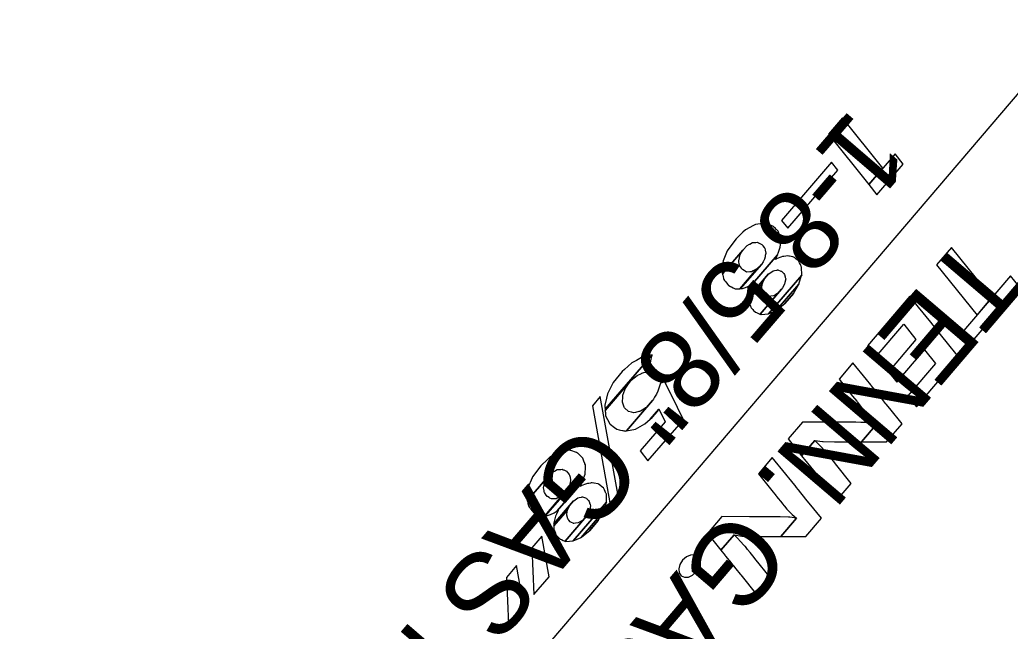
# Model space of a CAD drawing. Extents: x 3962991 to 3983549, y 181631 to 204078.
# Drawn here: x 3970389 to 3970895, y 196655 to 196968 of the extents above; entities that cross this region are included whole.
import ezdxf

# ---------------------------------------------------------------- set-up
doc = ezdxf.new("R2010")
doc.units = 0
for name, color, linetype in [('V-ANNO-MASK', 7, 'Continuous'), ('V-ANNO-MASK2', 7, 'Continuous'), ('V-UTIL-IDEN', 7, 'Continuous'), ('V-UTIL-LINE', 7, 'Continuous')]:
    doc.layers.add(name, color=color, linetype=linetype)

msp = doc.modelspace()

# ---------------------------------------------------------------- linework, layer by layer
at = {"layer": 'V-ANNO-MASK2'}
for points in [[(3970830.22, 196891.79), (3970809.67, 196917.48), (3970802.46, 196909.1), (3970823.01, 196883.41)], [(3970840.72, 196893.86), (3970836.52, 196899.13), (3970823.01, 196883.41), (3970827.21, 196878.14)], [(3970807.3, 196890.7), (3970804.05, 196894.76), (3970778.46, 196864.97), (3970781.7, 196860.92)], [(3970758.68, 196858.95), (3970755.12, 196855.59), (3970750.89, 196849.88), (3970750.65, 196849.33), (3970748.45, 196844.25), (3970748.36, 196843.47), (3970747.86, 196839.08), (3970748.1, 196838.07), (3970748.19, 196837.68), (3970758.53, 196849.71), (3970760.9, 196852.2), (3970762.09, 196852.85), (3970762.1, 196852.85), (3970763.47, 196853.59), (3970764.68, 196853.68), (3970765.29, 196853.73), (3970766.09, 196853.79), (3970766.58, 196853.56), (3970766.91, 196853.39), (3970768.32, 196852.71), (3970768.82, 196852.06), (3970768.9, 196851.96), (3970769.53, 196851.15), (3970769.82, 196850.75), (3970770.04, 196849.65), (3970770.34, 196848.12), (3970770.31, 196848), (3970770.1, 196846.95), (3970769.96, 196846.26), (3970769.74, 196845.18), (3970768.94, 196843.8), (3970768.16, 196842.47), (3970757.46, 196830.02), (3970758.51, 196830.05), (3970759.99, 196830.64), (3970761.98, 196831.43), (3970763.55, 196832.46), (3970776.39, 196847.39), (3970776.85, 196848.73), (3970777.72, 196851.27), (3970777.81, 196852.5), (3970777.89, 196853.79), (3970777.93, 196854.27), (3970777.96, 196854.75), (3970778.02, 196855.64), (3970777.89, 196856.02), (3970777.68, 196856.58), (3970777.66, 196856.65), (3970777.18, 196857.96), (3970776.83, 196858.9), (3970776.64, 196859.42), (3970775.92, 196860.13), (3970775.83, 196860.22), (3970775.26, 196860.78), (3970774.17, 196861.85), (3970773.92, 196862.09), (3970773.39, 196862.28), (3970772.81, 196862.49), (3970772.38, 196862.65), (3970771.52, 196862.95), (3970770.95, 196863.15), (3970770.47, 196863.33), (3970770.28, 196863.39), (3970769.96, 196863.5), (3970768.73, 196863.36), (3970765.08, 196862.92), (3970763.99, 196862.33), (3970759.92, 196860.12)], [(3970758.12, 196848.97), (3970758.53, 196849.71), (3970748.19, 196837.68), (3970748.24, 196837.46), (3970748.24, 196837.47), (3970748.37, 196836.88), (3970748.38, 196836.89), (3970748.53, 196836.2), (3970748.77, 196835.17), (3970748.89, 196834.65), (3970749.26, 196834.21), (3970749.6, 196833.8), (3970749.83, 196833.52), (3970750.8, 196832.33), (3970751.32, 196831.7), (3970751.4, 196831.6), (3970752.33, 196831.14), (3970752.34, 196831.14), (3970752.78, 196830.92), (3970753.6, 196830.52), (3970754.72, 196829.96), (3970754.78, 196829.92), (3970755.49, 196829.95), (3970755.96, 196829.96), (3970756.68, 196829.99), (3970757.08, 196830), (3970765.78, 196840.13), (3970765.08, 196839.77), (3970763.81, 196839.1), (3970762.98, 196838.67), (3970762.27, 196838.64), (3970762.18, 196838.64), (3970760.5, 196838.55), (3970759.74, 196839.01), (3970759.31, 196839.26), (3970758.44, 196839.78), (3970758.32, 196839.85), (3970757.85, 196840.53), (3970756.96, 196841.81), (3970756.88, 196842.26), (3970756.76, 196842.93), (3970756.63, 196843.65), (3970756.52, 196844.2), (3970756.83, 196845.86), (3970757.03, 196846.95)], [(3970776.21, 196847.02), (3970776.38, 196847.39), (3970763.55, 196832.46), (3970763.9, 196832.68), (3970763.12, 196830.84), (3970762.63, 196829.69), (3970762.1, 196827.73), (3970761.74, 196826.38), (3970761.75, 196825.83), (3970771.82, 196837.55), (3970771.98, 196837.66), (3970774.08, 196839.08), (3970774.12, 196839.09), (3970774.75, 196839.24), (3970775.98, 196839.52), (3970776.23, 196839.57), (3970776.23, 196839.58), (3970776.44, 196839.62), (3970778.04, 196839.06), (3970778.33, 196838.95), (3970778.34, 196838.96), (3970778.47, 196838.9), (3970778.72, 196838.63), (3970779.55, 196837.71), (3970779.93, 196837.29), (3970780.24, 196836.12), (3970780.32, 196835.86), (3970780.35, 196835.72), (3970780.53, 196835.05), (3970780.17, 196833.2), (3970779.98, 196832.26), (3970778.94, 196830.48), (3970778.47, 196829.68), (3970767.54, 196816.96), (3970767.88, 196816.82), (3970767.92, 196816.82), (3970771.68, 196817.1), (3970788.73, 196836.93), (3970788.67, 196840.97), (3970788.67, 196841), (3970788.5, 196841.36), (3970788.42, 196841.52), (3970788.25, 196841.89), (3970788.04, 196842.36), (3970787.61, 196843.29), (3970787.34, 196843.85), (3970787.29, 196843.97), (3970787.18, 196844.2), (3970786.4, 196844.82), (3970785.95, 196845.17), (3970784.99, 196845.92), (3970784.7, 196846.15), (3970784.59, 196846.23), (3970784.26, 196846.3), (3970782.47, 196846.64), (3970782.32, 196846.67), (3970782.15, 196846.7), (3970781.3, 196846.86), (3970780.69, 196846.74), (3970780.66, 196846.74), (3970779.61, 196846.53), (3970779.53, 196846.52), (3970778.95, 196846.41), (3970777.99, 196846.22), (3970776.13, 196845.39), (3970775.31, 196845.03)], [(3970886.13, 196825.47), (3970865.39, 196851.15), (3970857.76, 196842.2), (3970878.49, 196816.52)], [(3970768.17, 196842.47), (3970765.78, 196840.13), (3970757.08, 196830), (3970757.46, 196830.02)], [(3970769.88, 196835.21), (3970771.82, 196837.55), (3970761.75, 196825.83), (3970761.75, 196825.75), (3970761.76, 196824.75), (3970761.76, 196824.71), (3970768.66, 196832.74), (3970768.7, 196832.83)], [(3970768.56, 196832.04), (3970768.66, 196832.74), (3970761.76, 196824.71), (3970761.77, 196824.13), (3970761.78, 196822.99), (3970761.84, 196822.83), (3970761.9, 196822.7), (3970762.54, 196821.02), (3970762.66, 196820.72), (3970762.71, 196820.56), (3970762.86, 196820.17), (3970763.72, 196819.3), (3970764.12, 196818.9), (3970764.83, 196818.18), (3970764.98, 196818.01), (3970765.1, 196817.97), (3970765.65, 196817.74), (3970766.56, 196817.37), (3970767.02, 196817.18), (3970767.37, 196817.02), (3970767.38, 196817.03), (3970767.53, 196816.96), (3970778.47, 196829.68), (3970776.42, 196827.55), (3970775.47, 196827.01), (3970774.25, 196826.32), (3970772.87, 196826.13), (3970772.01, 196826.02), (3970771.91, 196826.07), (3970771.69, 196826.17), (3970770.72, 196826.58), (3970770.17, 196826.81), (3970769.38, 196827.76), (3970769.15, 196828.05), (3970769.06, 196828.16), (3970768.86, 196828.39), (3970768.37, 196830.24), (3970768.33, 196830.38), (3970768.37, 196830.67)], [(3970788.71, 196836.87), (3970788.72, 196836.93), (3970771.68, 196817.1), (3970771.71, 196817.09), (3970775.7, 196818.88), (3970787.31, 196832.4)], [(3970787.03, 196831.91), (3970787.31, 196832.39), (3970775.7, 196818.88), (3970775.91, 196818.98), (3970780.15, 196822.46), (3970784.45, 196827.47)], [(3970899.97, 196831.09), (3970895.58, 196836.56), (3970869.72, 196806.23), (3970874.11, 196800.76)], [(3970780.43, 196822.69), (3970784.45, 196827.46), (3970780.15, 196822.46)], [(3970848.49, 196820.61), (3970844.04, 196826.11), (3970822.38, 196800.71), (3970826.82, 196795.2), (3970840.93, 196811.75), (3970847.21, 196803.99), (3970833.1, 196787.44), (3970837.44, 196782.07), (3970851.54, 196798.62), (3970857.19, 196791.61), (3970843.08, 196775.06), (3970847.51, 196769.56), (3970869.17, 196794.97), (3970864.74, 196800.46), (3970859.09, 196807.47), (3970854.76, 196812.84)], [(3970698.04, 196788.68), (3970696.89, 196787.66), (3970692.28, 196781.98), (3970691.07, 196779.55), (3970689.35, 196776.13), (3970688.83, 196773.92), (3970687.97, 196770.32), (3970688, 196769.9), (3970688.12, 196768.25), (3970712.13, 196796.2), (3970710.31, 196795.85), (3970709.76, 196795.68), (3970706.7, 196794.72), (3970704.1, 196793.29), (3970701.78, 196792.02)], [(3970711.97, 196795.26), (3970712.13, 196796.19), (3970688.12, 196768.25), (3970688.17, 196767.57), (3970701.35, 196782.91), (3970703.04, 196784.33), (3970704.54, 196785.59), (3970706.7, 196786.55), (3970706.71, 196786.56), (3970706.97, 196786.68), (3970707.85, 196787.07), (3970710.28, 196787.46), (3970710.59, 196787.51), (3970710.66, 196787.91), (3970711.21, 196790.98), (3970711.35, 196791.77), (3970711.39, 196792.01), (3970711.74, 196793.96), (3970711.85, 196794.57)], [(3970821.89, 196783.43), (3970814.96, 196792), (3970807.87, 196783.69), (3970814.74, 196775.04), (3970816.9, 196772.33), (3970817.11, 196772.06), (3970817.11, 196772.06), (3970819.93, 196768.5), (3970820.01, 196768.4), (3970821.12, 196767), (3970822.47, 196765.56), (3970824.74, 196763.12), (3970825.15, 196762.77), (3970827.31, 196760.88), (3970819.36, 196751.55), (3970832.16, 196751.56), (3970840.09, 196760.86), (3970833.87, 196768.57), (3970832.04, 196770.85), (3970831.7, 196771.28), (3970829.58, 196773.89), (3970828.33, 196775.45), (3970827.2, 196776.84), (3970827.13, 196776.94), (3970824.28, 196780.47), (3970824.07, 196780.73)], [(3970698.63, 196779.19), (3970701.35, 196782.91), (3970688.17, 196767.57), (3970688.2, 196767.06), (3970688.24, 196766.61), (3970688.34, 196765.19), (3970688.35, 196765.01), (3970688.55, 196764.62), (3970689.32, 196763.07), (3970690.46, 196760.77), (3970690.71, 196760.58), (3970692.94, 196758.86), (3970694.05, 196758), (3970695.31, 196757.74), (3970695.32, 196757.75), (3970695.9, 196757.62), (3970697.07, 196757.38), (3970697.25, 196757.34), (3970697.62, 196757.27), (3970698.22, 196757.15), (3970698.56, 196757.07), (3970698.87, 196757.14), (3970699.08, 196757.18), (3970712.44, 196772.73), (3970709.42, 196769.41), (3970708.83, 196769.01), (3970707.87, 196768.37), (3970706.2, 196767.24), (3970705.66, 196767.12), (3970705.38, 196767.06), (3970703.66, 196766.65), (3970702.8, 196766.45), (3970701.59, 196766.78), (3970700.08, 196767.18), (3970698, 196769.06), (3970697.88, 196769.39), (3970696.93, 196771.92), (3970697.11, 196774.57), (3970697.16, 196775.25), (3970697.17, 196775.46), (3970698.28, 196778.29)], [(3970718.41, 196782.21), (3970716.49, 196781.58), (3970715.67, 196779.03), (3970715.47, 196778.55), (3970715.48, 196778.55), (3970715.09, 196777.59), (3970714.46, 196776.04), (3970713.47, 196774.42), (3970712.85, 196773.4), (3970712.43, 196772.72), (3970699.08, 196757.18), (3970703.62, 196758.12), (3970708.48, 196760.75), (3970711.16, 196763.16), (3970715.61, 196768.34), (3970715.69, 196768.18), (3970718.8, 196761.78), (3970706.02, 196746.9), (3970710.05, 196741.81), (3970728.15, 196762.88), (3970725.12, 196769.13), (3970722.01, 196775.53), (3970721.93, 196775.69), (3970721.72, 196776.14), (3970720.77, 196778.07), (3970719.42, 196780.86), (3970719.36, 196780.98), (3970719.27, 196781.17), (3970719.12, 196781.46), (3970718.87, 196781.99), (3970718.71, 196782.31)], [(3970695.02, 196723.15), (3970685.66, 196774.75), (3970681.59, 196770.01), (3970690.95, 196718.42)], [(3970714.84, 196767.19), (3970715.61, 196768.34), (3970711.16, 196763.16), (3970712.13, 196764.03)], [(3970712.58, 196764.43), (3970714.84, 196767.18), (3970712.13, 196764.03), (3970712.57, 196764.43)], [(3970803.32, 196761.65), (3970789.16, 196761.73), (3970781.74, 196753.03), (3970788.66, 196744.45), (3970795.38, 196752.34), (3970799.32, 196751.7), (3970799.75, 196751.7), (3970805.47, 196751.55), (3970805.64, 196751.55), (3970807.95, 196751.55), (3970810.53, 196751.55), (3970814.88, 196751.55), (3970815.58, 196751.55), (3970819.36, 196751.55), (3970827.31, 196760.88), (3970823.96, 196761.38), (3970823.28, 196761.41), (3970819.06, 196761.56), (3970816.5, 196761.58), (3970814.21, 196761.59), (3970814.04, 196761.59), (3970808.21, 196761.62), (3970807.78, 196761.63)], [(3970797.83, 196749.95), (3970795.38, 196752.34), (3970788.66, 196744.45), (3970790.84, 196741.75), (3970791.05, 196741.49), (3970793.9, 196737.97), (3970793.98, 196737.86), (3970795.1, 196736.47), (3970796.35, 196734.92), (3970798.47, 196732.3), (3970798.8, 196731.87), (3970798.81, 196731.88), (3970806.86, 196721.88), (3970814.05, 196730.31), (3970806.01, 196740.32), (3970805.67, 196740.75), (3970803.56, 196743.37), (3970802.31, 196744.93), (3970801.18, 196746.32), (3970801.1, 196746.41), (3970798.06, 196749.72)], [(3970658.78, 196742.7), (3970655.22, 196739.35), (3970650.99, 196733.64), (3970650.75, 196733.09), (3970648.55, 196728.01), (3970648.46, 196727.22), (3970647.96, 196722.83), (3970648.2, 196721.82), (3970648.29, 196721.44), (3970658.63, 196733.47), (3970661, 196735.96), (3970662.19, 196736.6), (3970662.2, 196736.61), (3970663.57, 196737.35), (3970664.78, 196737.44), (3970665.39, 196737.49), (3970666.19, 196737.54), (3970666.68, 196737.31), (3970667.01, 196737.15), (3970668.42, 196736.47), (3970668.92, 196735.82), (3970669, 196735.72), (3970669.63, 196734.9), (3970669.92, 196734.5), (3970670.14, 196733.41), (3970670.44, 196731.88), (3970670.41, 196731.76), (3970670.2, 196730.71), (3970670.06, 196730.02), (3970669.84, 196728.94), (3970669.04, 196727.56), (3970668.26, 196726.22), (3970657.56, 196713.77), (3970658.61, 196713.8), (3970660.09, 196714.4), (3970662.08, 196715.18), (3970663.65, 196716.22), (3970676.49, 196731.15), (3970676.95, 196732.48), (3970677.82, 196735.03), (3970677.91, 196736.26), (3970678, 196737.55), (3970678.03, 196738.02), (3970678.06, 196738.51), (3970678.12, 196739.4), (3970677.99, 196739.77), (3970677.79, 196740.33), (3970677.76, 196740.4), (3970677.28, 196741.72), (3970676.93, 196742.66), (3970676.74, 196743.18), (3970676.02, 196743.89), (3970675.93, 196743.98), (3970675.36, 196744.54), (3970674.28, 196745.6), (3970674.02, 196745.85), (3970673.49, 196746.04), (3970672.91, 196746.25), (3970672.48, 196746.4), (3970671.62, 196746.71), (3970671.05, 196746.91), (3970670.57, 196747.09), (3970670.38, 196747.15), (3970670.06, 196747.26), (3970668.83, 196747.12), (3970665.18, 196746.68), (3970664.09, 196746.09), (3970660.02, 196743.88)], [(3970780.6, 196735), (3970773.68, 196743.58), (3970766.59, 196735.26), (3970773.45, 196726.62), (3970775.62, 196723.9), (3970775.82, 196723.63), (3970775.83, 196723.64), (3970778.65, 196720.08), (3970778.73, 196719.97), (3970779.84, 196718.57), (3970781.19, 196717.13), (3970783.46, 196714.69), (3970783.86, 196714.35), (3970786.03, 196712.45), (3970778.08, 196703.13), (3970790.88, 196703.13), (3970798.81, 196712.43), (3970792.59, 196720.15), (3970790.75, 196722.43), (3970790.41, 196722.85), (3970788.29, 196725.47), (3970787.04, 196727.02), (3970785.92, 196728.41), (3970785.84, 196728.52), (3970782.99, 196732.04), (3970782.78, 196732.3)], [(3970658.23, 196732.73), (3970658.63, 196733.47), (3970648.29, 196721.44), (3970648.34, 196721.22), (3970648.34, 196721.23), (3970648.47, 196720.63), (3970648.48, 196720.64), (3970648.63, 196719.96), (3970648.87, 196718.93), (3970648.99, 196718.4), (3970649.36, 196717.96), (3970649.7, 196717.55), (3970649.93, 196717.27), (3970650.91, 196716.09), (3970651.42, 196715.46), (3970651.5, 196715.36), (3970652.43, 196714.89), (3970652.44, 196714.9), (3970652.88, 196714.67), (3970653.7, 196714.27), (3970654.82, 196713.71), (3970654.88, 196713.68), (3970655.59, 196713.7), (3970656.06, 196713.72), (3970656.78, 196713.74), (3970657.18, 196713.76), (3970665.89, 196723.89), (3970665.18, 196723.52), (3970663.91, 196722.86), (3970663.08, 196722.43), (3970662.37, 196722.39), (3970662.28, 196722.39), (3970660.6, 196722.31), (3970659.84, 196722.77), (3970659.41, 196723.02), (3970658.54, 196723.54), (3970658.42, 196723.6), (3970657.95, 196724.28), (3970657.06, 196725.57), (3970656.98, 196726.02), (3970656.86, 196726.68), (3970656.73, 196727.41), (3970656.62, 196727.95), (3970656.93, 196729.62), (3970657.13, 196730.71)], [(3970676.31, 196730.77), (3970676.48, 196731.14), (3970663.65, 196716.22), (3970664, 196716.44), (3970663.22, 196714.6), (3970662.73, 196713.45), (3970662.2, 196711.48), (3970661.84, 196710.14), (3970661.85, 196709.58), (3970671.92, 196721.3), (3970672.08, 196721.42), (3970674.18, 196722.84), (3970674.22, 196722.85), (3970674.85, 196722.99), (3970676.08, 196723.28), (3970676.33, 196723.33), (3970676.33, 196723.34), (3970676.54, 196723.38), (3970678.14, 196722.82), (3970678.43, 196722.71), (3970678.44, 196722.72), (3970678.57, 196722.66), (3970678.82, 196722.38), (3970679.65, 196721.47), (3970680.03, 196721.05), (3970680.34, 196719.88), (3970680.42, 196719.61), (3970680.45, 196719.47), (3970680.63, 196718.81), (3970680.27, 196716.96), (3970680.08, 196716.02), (3970679.04, 196714.24), (3970678.57, 196713.44), (3970667.64, 196700.72), (3970667.98, 196700.57), (3970668.02, 196700.58), (3970671.78, 196700.85), (3970688.83, 196720.69), (3970688.77, 196724.73), (3970688.77, 196724.76), (3970688.6, 196725.11), (3970688.53, 196725.28), (3970688.35, 196725.64), (3970688.14, 196726.11), (3970687.71, 196727.04), (3970687.44, 196727.61), (3970687.39, 196727.73), (3970687.28, 196727.95), (3970686.5, 196728.58), (3970686.05, 196728.92), (3970685.09, 196729.68), (3970684.8, 196729.91), (3970684.69, 196729.99), (3970684.36, 196730.06), (3970682.57, 196730.4), (3970682.43, 196730.42), (3970682.25, 196730.45), (3970681.4, 196730.61), (3970680.79, 196730.5), (3970680.76, 196730.49), (3970679.71, 196730.29), (3970679.63, 196730.27), (3970679.05, 196730.16), (3970678.1, 196729.97), (3970676.23, 196729.15), (3970675.41, 196728.78)], [(3970668.27, 196726.23), (3970665.88, 196723.88), (3970657.18, 196713.76), (3970657.56, 196713.77)], [(3970669.98, 196718.97), (3970671.92, 196721.3), (3970661.85, 196709.58), (3970661.85, 196709.51), (3970661.86, 196708.51), (3970661.86, 196708.47), (3970668.76, 196716.5), (3970668.8, 196716.59)], [(3970688.81, 196720.63), (3970688.82, 196720.68), (3970671.78, 196700.85), (3970671.81, 196700.85), (3970675.8, 196702.64), (3970687.41, 196716.15)], [(3970668.66, 196715.8), (3970668.76, 196716.49), (3970661.86, 196708.47), (3970661.87, 196707.89), (3970661.88, 196706.75), (3970661.94, 196706.59), (3970662, 196706.46), (3970662.64, 196704.78), (3970662.76, 196704.47), (3970662.81, 196704.32), (3970662.96, 196703.93), (3970663.82, 196703.06), (3970664.22, 196702.66), (3970664.93, 196701.94), (3970665.08, 196701.77), (3970665.2, 196701.73), (3970665.75, 196701.49), (3970666.66, 196701.12), (3970667.12, 196700.93), (3970667.47, 196700.78), (3970667.48, 196700.79), (3970667.63, 196700.71), (3970678.57, 196713.44), (3970676.52, 196711.31), (3970675.57, 196710.77), (3970674.35, 196710.08), (3970672.97, 196709.89), (3970672.11, 196709.77), (3970672.01, 196709.83), (3970671.79, 196709.92), (3970670.82, 196710.34), (3970670.27, 196710.56), (3970669.48, 196711.52), (3970669.25, 196711.81), (3970669.16, 196711.92), (3970668.97, 196712.14), (3970668.47, 196713.99), (3970668.43, 196714.14), (3970668.47, 196714.42)], [(3970687.13, 196715.67), (3970687.41, 196716.15), (3970675.8, 196702.64), (3970676.01, 196702.73), (3970680.25, 196706.21), (3970684.55, 196711.23)], [(3970680.53, 196706.45), (3970684.55, 196711.22), (3970680.25, 196706.21)], [(3970762.03, 196713.22), (3970747.87, 196713.3), (3970740.45, 196704.6), (3970747.37, 196696.03), (3970754.1, 196703.91), (3970758.04, 196703.28), (3970758.46, 196703.27), (3970764.19, 196703.12), (3970764.36, 196703.12), (3970766.67, 196703.12), (3970769.24, 196703.12), (3970773.6, 196703.13), (3970774.3, 196703.13), (3970778.08, 196703.13), (3970786.03, 196712.45), (3970782.67, 196712.95), (3970782, 196712.98), (3970777.78, 196713.13), (3970775.22, 196713.15), (3970772.92, 196713.16), (3970772.75, 196713.16), (3970766.93, 196713.2), (3970766.5, 196713.2)], [(3970659.51, 196682.42), (3970655.77, 196703.27), (3970650.59, 196697.25), (3970651.69, 196673.32)], [(3970756.54, 196701.53), (3970754.1, 196703.91), (3970747.37, 196696.03), (3970749.56, 196693.33), (3970749.77, 196693.06), (3970752.61, 196689.54), (3970752.69, 196689.44), (3970753.82, 196688.05), (3970755.07, 196686.49), (3970757.18, 196683.87), (3970757.52, 196683.44), (3970757.53, 196683.45), (3970765.58, 196673.46), (3970772.76, 196681.88), (3970764.72, 196691.89), (3970764.38, 196692.32), (3970762.27, 196694.95), (3970761.02, 196696.5), (3970759.9, 196697.89), (3970759.81, 196697.99), (3970756.78, 196701.29)], [(3970729.7, 196692.64), (3970727.8, 196690.94), (3970726.43, 196688.8), (3970725.82, 196686.52), (3970726.02, 196684.48), (3970727.04, 196682.97), (3970728.71, 196682.19), (3970730.75, 196682.31), (3970732.88, 196683.3), (3970734.79, 196684.99), (3970736.15, 196687.14), (3970736.79, 196689.4), (3970736.59, 196691.44), (3970735.57, 196692.97), (3970733.9, 196693.72), (3970731.86, 196693.6)], [(3970646.53, 196667.32), (3970642.79, 196688.17), (3970637.62, 196682.15), (3970638.71, 196658.22)]]:
    msp.add_lwpolyline(points, close=True, dxfattribs=at)
at = {"layer": 'V-UTIL-LINE'}
msp.add_line((3970065.58, 195951.74), (3971473.5, 197603.23), dxfattribs=at)

# ---------------------------------------------------------------- texts
at = {"layer": 'V-ANNO-MASK'}
for s, rotation, p in [('1-8 5/8" GAS PIPELINE', 229.3244, (3970814.54, 196923.15)), ('TENN. GAS TRANS. CO.', 229.5519, (3970872.53, 196859.53))]:
    msp.add_text(s, height=41.9999, rotation=rotation, dxfattribs=at).set_placement(p)
at = {"layer": 'V-UTIL-IDEN'}
for s, rotation, p in [('1-8 5/8" GAS PIPELINE', 229.3244, (3970814.54, 196923.15)), ('TENN. GAS TRANS. CO.', 229.5519, (3970872.53, 196859.53))]:
    msp.add_text(s, height=41.9999, rotation=rotation, dxfattribs=at).set_placement(p)

doc.saveas('drawing.dxf')
